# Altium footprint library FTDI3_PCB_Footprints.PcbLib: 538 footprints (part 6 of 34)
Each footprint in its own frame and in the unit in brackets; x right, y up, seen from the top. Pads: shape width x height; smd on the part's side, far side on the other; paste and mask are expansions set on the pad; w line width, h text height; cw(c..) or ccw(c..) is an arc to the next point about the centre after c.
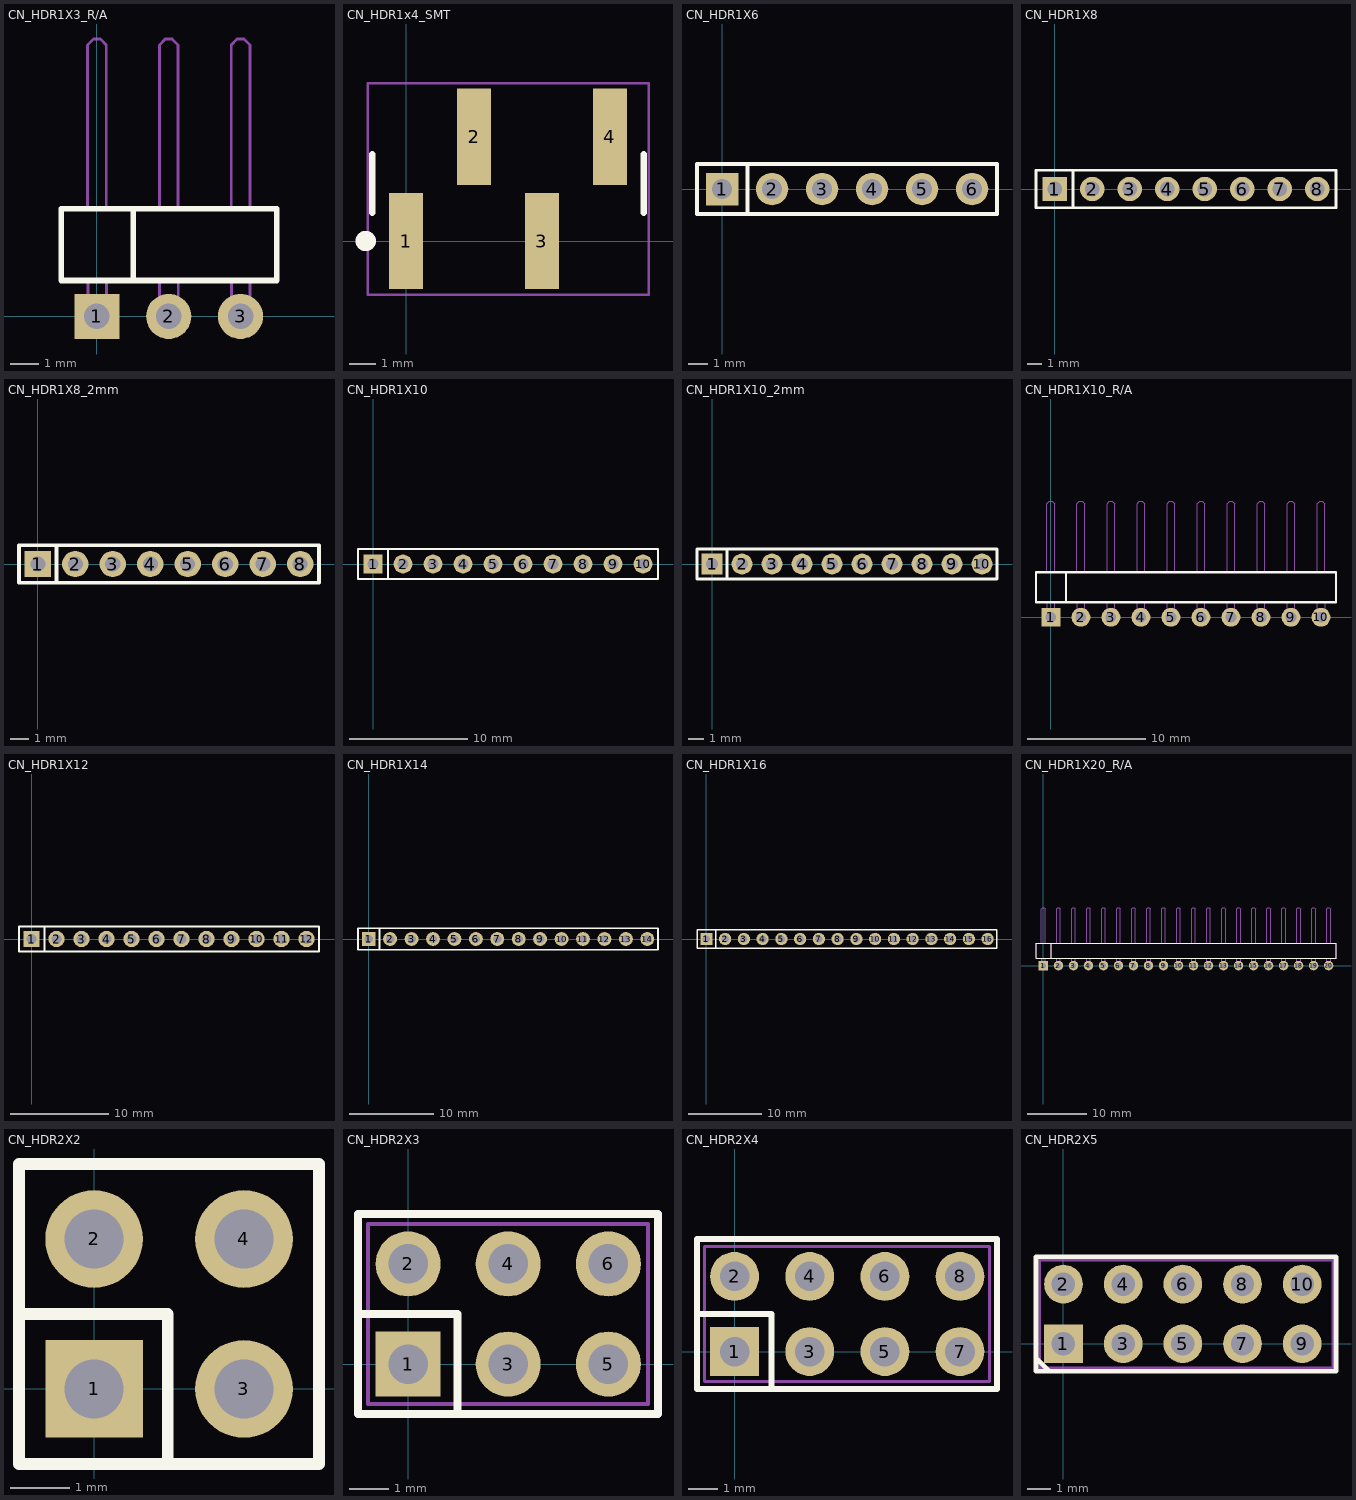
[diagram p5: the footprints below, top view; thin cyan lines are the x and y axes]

## CN_HDR1X3_R/A [mm] "Connector; Header; 3 Position; pitch 0.1\"; R/A"
pads (3):
  rect 1.6x1.6 hole 0.9: 1(0,0)
  round 1.6 hole 0.9: 2(2.54,0) 3(5.08,0)
Top Overlay:
  lines w0.2: 1.28,1.27 1.28,3.81 ; -1.26,1.27 6.36,1.27 6.36,3.81 -1.26,3.81 -1.26,1.27
M13_Assembly_Info:
  lines w0.1: -0.33,3.81 -0.33,9.602 -0.122,9.81 0.122,9.81 0.33,9.602 0.33,3.81 ; -0.32,1.27 -0.32,-0.33 0.34,-0.33 0.34,1.27 ; 1.28,1.27 1.28,3.81 ; 2.21,3.81 2.21,9.602 2.418,9.81 2.662,9.81 2.87,9.602 2.87,3.81 ; 2.22,1.27 2.22,-0.33 2.88,-0.33 2.88,1.27 ; 4.75,3.81 4.75,9.602 4.958,9.81 5.202,9.81 5.41,9.602 5.41,3.81 ; 4.76,1.27 4.76,-0.33 5.42,-0.33 5.42,1.27 ; -1.26,1.27 6.36,1.27 6.36,3.81 -1.26,3.81 -1.26,1.27

## CN_HDR1x4_SMT [mm]
pads (4):
  rect 1.27x3.6 smd: 1(0,0) 2(2.54,3.9) 3(5.08,0) 4(7.62,3.9)
Top Overlay:
  circle w0.5: c-1.51,0 r0.13
  lines w0.254: -1.27,1.06 -1.27,3.23 ; 8.89,1.06 8.89,3.23
M15_Country_Yard:
  lines w0.1: -1.44,-2.01 9.07,-2 9.07,5.9 -1.44,5.9 -1.44,-2.01

## CN_HDR1X6 [mil] "Connector; Header; 6 Position; pitch 0.1\""
pads (6):
  rect 65x65 hole 39.37: 1(0,0)
  round 65 hole 39.37: 2(100,0) 3(200,0) 4(300,0) 5(400,0) 6(500,0)
Top Overlay:
  lines w7.87: 51.18,-50 51.18,50 ; -50,-50 -50,50 550,50 550,-50 -50,-50

## CN_HDR1X8 [mil] "Connector; Header; 8 Position; pitch 0.1\""
pads (8):
  rect 65x65 hole 39.37: 1(0,0)
  round 65 hole 39.37: 2(100,0) 3(200,0) 4(300,0) 5(400,0) 6(500,0) 7(600,0) 8(700,0)
Top Overlay:
  lines w7.87: 49.21,-50 49.21,50 ; -50,-50 -50,50 750,50 750,-50 -50,-50

## CN_HDR1X8_2mm [mm] "Connector; Header; 8 Positions; pitch 2.0mm"
pads (8):
  rect 1.4x1.4 hole 0.8: 1(0,0)
  round 1.4 hole 0.8: 2(2,0) 3(4,0) 4(6,0) 5(8,0) 6(10,0) 7(12,0) 8(14,0)
Top Overlay:
  lines w0.2: 1,-1 1,1 ; -1,-1 -1,1 15,1 15,-1 -1,-1

## CN_HDR1X10 [mm] "Connector; Header; 10 Position; pitch 0.1\""
pads (10):
  rect 1.6x1.6 hole 0.9: 1(0,0)
  round 1.6 hole 0.9: 2(2.54,0) 3(5.08,0) 4(7.62,0) 5(10.16,0) 6(12.7,0) 7(15.24,0) 8(17.78,0) 9(20.32,0) 10(22.86,0)
Top Overlay:
  lines w0.2: 1.275,-1.27 1.275,1.27 ; -1.27,-1.27 24.13,-1.27 24.13,1.27 0.635,1.27 -1.27,1.27 -1.27,-1.27

## CN_HDR1X10_2mm [mm] "Connector; Header; 10 Position; pitch 2.0mm"
pads (10):
  rect 1.4x1.4 hole 0.8: 1(0,0)
  round 1.4 hole 0.8: 2(2,0) 3(4,0) 4(6,0) 5(8,0) 6(10,0) 7(12,0) 8(14,0) 9(16,0) 10(18,0)
Top Overlay:
  lines w0.2: 1,-1 1,1 ; -1,-1 19,-1 19,1 -1,1 -1,-1

## CN_HDR1X10_R/A [mm] "Connector; Header; 10 Position; pitch 0.1\"; R/A"
pads (10):
  rect 1.6x1.6 hole 0.9: 1(0,0)
  round 1.6 hole 0.9: 2(2.54,0) 3(5.08,0) 4(7.62,0) 5(10.16,0) 6(12.7,0) 7(15.24,0) 8(17.78,0) 9(20.32,0) 10(22.86,0)
Top Overlay:
  lines w0.2: 1.28,1.27 1.28,3.81 ; -1.26,1.27 24.13,1.27 24.13,3.81 -1.26,3.81 -1.26,1.27
M13_Assembly_Info:
  lines w0.1: -0.33,3.81 -0.33,9.602 -0.122,9.81 0.122,9.81 0.33,9.602 0.33,3.81 ; -0.32,1.27 -0.32,-0.33 0.34,-0.33 0.34,1.27 ; 1.28,1.27 1.28,3.81 ; 2.21,3.81 2.21,9.602 2.418,9.81 2.662,9.81 2.87,9.602 2.87,3.81 ; 2.22,1.27 2.22,-0.33 2.88,-0.33 2.88,1.27 ; 4.75,3.81 4.75,9.602 4.958,9.81 5.202,9.81 5.41,9.602 5.41,3.81 ; 4.76,1.27 4.76,-0.33 5.42,-0.33 5.42,1.27 ; 7.29,3.81 7.29,9.602 7.498,9.81 7.742,9.81 7.95,9.602 7.95,3.81 ; 7.3,1.27 7.3,-0.33 7.96,-0.33 7.96,1.27 ; 9.83,3.81 9.83,9.602 10.038,9.81 10.282,9.81 10.49,9.602 10.49,3.81 ; 9.84,1.27 9.84,-0.33 10.5,-0.33 10.5,1.27 ; 12.37,3.81 12.37,9.602 12.578,9.81 12.822,9.81 13.03,9.602 13.03,3.81 ; 12.38,1.27 12.38,-0.33 13.04,-0.33 13.04,1.27 ; 14.91,3.81 14.91,9.602 15.118,9.81 15.362,9.81 15.57,9.602 15.57,3.81 ; 14.92,1.27 14.92,-0.33 15.58,-0.33 15.58,1.27 ; 17.45,3.81 17.45,9.602 17.658,9.81 17.902,9.81 18.11,9.602 18.11,3.81 ; 17.46,1.27 17.46,-0.33 18.12,-0.33 18.12,1.27 ; 19.99,3.81 19.99,9.602 20.198,9.81 20.442,9.81 20.65,9.602 20.65,3.81 ; 20,1.27 20,-0.33 20.66,-0.33 20.66,1.27 ; 22.53,3.81 22.53,9.602 22.738,9.81 22.982,9.81 23.19,9.602 23.19,3.81 ; 22.54,1.27 22.54,-0.33 23.2,-0.33 23.2,1.27 ; -1.26,1.27 24.13,1.27 24.13,3.81 -1.26,3.81 -1.26,1.27

## CN_HDR1X12 [mil] "Connector; Header; 12 Position; pitch 0.1\""
pads (12):
  rect 65x65 hole 39.37: 1(0,0)
  round 65 hole 39.37: 2(100,0) 3(200,0) 4(300,0) 5(400,0) 6(500,0) 7(600,0) 8(700,0) 9(800,0) 10(900,0) 11(1000,0) 12(1100,0)
Top Overlay:
  lines w7.87: 51.18,-50 51.18,50 ; -50,-50 1150,-50 1150,50 25,50 -50,50 -50,-50

## CN_HDR1X14 [mil] "Connector; Header; 14 Position; pitch 0.1\""
pads (14):
  rect 65x65 hole 39.37: 1(0,0)
  round 65 hole 39.37: 2(100,0) 3(200,0) 4(300,0) 5(400,0) 6(500,0) 7(600,0) 8(700,0) 9(800,0) 10(900,0) 11(1000,0) 12(1100,0) 13(1200,0) 14(1300,0)
Top Overlay:
  lines w7.87: 50.2,-50 50.2,50 ; -50,-50 1350,-50 1350,50 25,50 -50,50 -50,-50

## CN_HDR1X16 [mil] "Connector; Header; 16 Position; pitch 0.1\""
pads (16):
  rect 65x65 hole 39.37: 1(0,0)
  round 65 hole 39.37: 2(100,0) 3(200,0) 4(300,0) 5(400,0) 6(500,0) 7(600,0) 8(700,0) 9(800,0) 10(900,0) 11(1000,0) 12(1100,0) 13(1200,0) 14(1300,0) 15(1400,0) 16(1500,0)
Top Overlay:
  lines w7.87: 50.2,-50 50.2,50 ; -50,-50 -50,50 25,50 1550,50 1550,-50 -50,-50

## CN_HDR1X20_R/A [mm] "Connector; Header; 20 Position; pitch 0.1\"; R/A"
height 2.54
pads (20):
  rect 1.6x1.6 hole 0.9: 1(0,0)
  round 1.6 hole 0.9: 2(2.54,0) 3(5.08,0) 4(7.62,0) 5(10.16,0) 6(12.7,0) 7(15.24,0) 8(17.78,0) 9(20.32,0) 10(22.86,0) 11(25.4,0) 12(27.94,0) 13(30.48,0) 14(33.02,0) 15(35.56,0) 16(38.1,0) 17(40.64,0) 18(43.18,0) 19(45.72,0) 20(48.26,0)
Top Overlay:
  lines w0.2: 1.28,1.27 1.28,3.81 ; -1.26,1.27 -1.26,3.81 49.51,3.81 49.51,1.27 -1.26,1.27
M13_Assembly_Info:
  drawing of 165 lines, arcs and shapes, not listed

## CN_HDR2X2 [mil] "Connector; Header; 2x2 Position; pitch 0.1\""
pads (4):
  rect 65x65 hole 39.37: 1(0,0)
  round 65 hole 39.37: 2(0,100) 3(100,0) 4(100,100)
Top Overlay:
  lines w7.87: -50,50 49.21,50 49.21,-50 ; -50,-50 150,-50 150,150 -50,150 -50,-50

## CN_HDR2X3 [mil] "Connector; Header; 2x3 Position; pitch 0.1\""
pads (6):
  rect 65x65 hole 39.37: 1(0,0)
  round 65 hole 39.37: 2(0,100) 3(100,0) 4(100,100) 5(200,0) 6(200,100)
Top Overlay:
  lines w7.87: -50,50 49.21,50 49.21,-50 ; -50,-50 249.61,-50 249.61,150 -50,150 -50,-50
M7_3D_Body:
  lines w3.94: -40,-40 -40,140 239.76,140 239.76,-40 -40,-40

## CN_HDR2X4 [mil] "Connector; Header; 2x4 Position; pitch 0.1\""
pads (8):
  rect 65x65 hole 39.37: 1(0,0)
  round 65 hole 39.37: 2(0,100) 3(100,0) 4(100,100) 5(200,0) 6(200,100) 7(300,0) 8(300,100)
Top Overlay:
  lines w7.87: -50,50 49.21,50 49.21,-50 ; -50,-50 -50,150 349.21,150 349.21,-50 -50,-50
M7_3D_Body:
  lines w3.94: -40,-40 339.37,-40 339.37,140 -40,140 -40,-40

## CN_HDR2X5 [mil] "Connector; Header; 2x5 Position; pitch 0.1\""
pads (10):
  rect 65x65 hole 39.37: 1(0,0)
  round 65 hole 39.37: 2(0,100) 3(100,0) 4(100,100) 5(200,0) 6(200,100) 7(300,0) 8(300,100) 9(400,0) 10(400,100)
Top Overlay:
  lines w7.87: -45.96,-23.92 -23.72,-46.16 ; -46.06,-46.06 -46.06,146.06 456.69,146.06 456.69,-46.06 -46.06,-46.06
M13_Assembly_Info:
  lines w3.94: -40,-40 450.79,-40 450.79,140 -40,140 -40,-40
